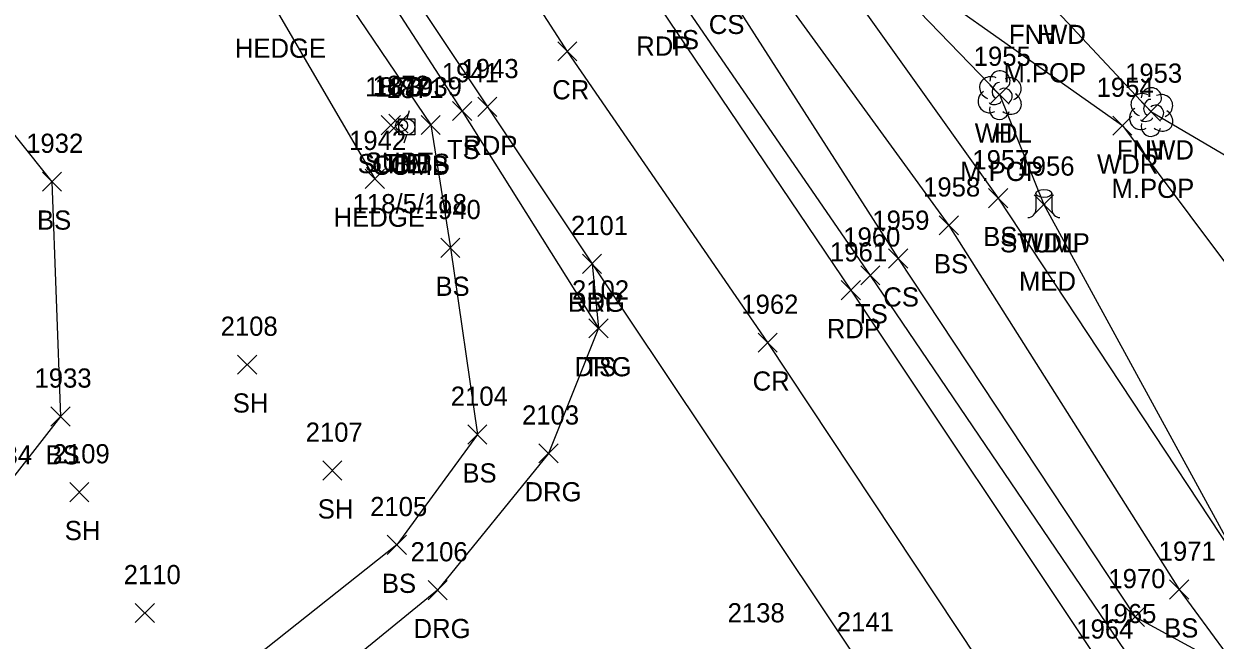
# Model space of a CAD drawing. Extents: x 1501299 to 1502485, y 381423 to 383765.
# Drawn here: x 1501473.5 to 1501597.6, y 383367.4 to 383431.6 of the extents above; entities that cross this region are included whole.
import ezdxf

# ---------------------------------------------------------------- set-up
doc = ezdxf.new("R2010")
doc.units = 0
for name, color, linetype in [('C_A', 7, 'Continuous'), ('C_I', 7, 'Continuous'), ('CBP', 7, 'Continuous'), ('L_A', 7, 'Continuous'), ('L_C', 7, 'Continuous'), ('L_I', 7, 'Continuous'), ('L_TIC', 7, 'Continuous'), ('LAHR', 7, 'Continuous'), ('LAWA', 7, 'Continuous'), ('LELB', 7, 'Continuous'), ('LFNC', 7, 'Continuous'), ('LTD', 7, 'Continuous'), ('LTS', 7, 'Continuous'), ('P_A', 7, 'Continuous'), ('P_I', 7, 'Continuous'), ('P_TIC', 7, 'Continuous'), ('PET', 7, 'Continuous'), ('PRC', 7, 'Continuous'), ('R_A', 7, 'Continuous'), ('R_I', 7, 'Continuous'), ('R_TIC', 7, 'Continuous'), ('RDG', 7, 'Continuous'), ('U_A', 7, 'Continuous'), ('U_C', 7, 'Continuous'), ('U_I', 7, 'Continuous'), ('U_TIC', 7, 'Continuous'), ('UP', 7, 'Continuous')]:
    doc.layers.add(name, color=color, linetype=linetype)

msp = doc.modelspace()

# ---------------------------------------------------------------- linework, layer by layer
at = {"layer": 'CBP'}
for radius in [0.625, 0.0833]:
    msp.add_circle((1501512.86, 383421.03), radius, dxfattribs=at)
at = {"layer": 'L_TIC'}
for points in [[(1501574.15, 383423.23), (1501576.15, 383425.23)], [(1501576.15, 383423.23), (1501574.15, 383425.23)], [(1501518.17, 383421.52), (1501520.17, 383423.52)], [(1501520.17, 383421.52), (1501518.17, 383423.52)], [(1501589.93, 383421.47), (1501591.93, 383423.47)], [(1501591.93, 383421.47), (1501589.93, 383423.47)], [(1501514.89, 383420.07), (1501516.89, 383422.07)], [(1501516.89, 383420.07), (1501514.89, 383422.07)], [(1501586.95, 383420), (1501588.95, 383422)], [(1501588.95, 383420), (1501586.95, 383422)], [(1501475.43, 383414.16), (1501477.43, 383416.16)], [(1501477.43, 383414.16), (1501475.43, 383416.16)], [(1501509.07, 383414.46), (1501511.07, 383416.46)], [(1501511.07, 383414.46), (1501509.07, 383416.46)], [(1501574.01, 383412.45), (1501576.01, 383414.45)], [(1501576.01, 383412.45), (1501574.01, 383414.45)], [(1501578.77, 383411.79), (1501580.77, 383413.79)], [(1501580.77, 383411.79), (1501578.77, 383413.79)], [(1501568.88, 383409.61), (1501570.88, 383411.61)], [(1501570.88, 383409.61), (1501568.88, 383411.61)], [(1501516.94, 383407.26), (1501518.94, 383409.26)], [(1501518.94, 383407.26), (1501516.94, 383409.26)], [(1501563.6, 383406.15), (1501565.6, 383408.15)], [(1501565.6, 383406.15), (1501563.6, 383408.15)], [(1501560.69, 383404.4), (1501562.69, 383406.4)], [(1501562.69, 383404.4), (1501560.69, 383406.4)], [(1501532.38, 383398.88), (1501534.38, 383400.88)], [(1501534.38, 383398.88), (1501532.38, 383400.88)], [(1501495.77, 383395.1), (1501497.77, 383397.1)], [(1501497.77, 383395.1), (1501495.77, 383397.1)], [(1501476.31, 383389.7), (1501478.31, 383391.7)], [(1501478.31, 383389.7), (1501476.31, 383391.7)], [(1501519.75, 383387.81), (1501521.75, 383389.81)], [(1501521.75, 383387.81), (1501519.75, 383389.81)], [(1501504.64, 383384.06), (1501506.64, 383386.06)], [(1501506.64, 383384.06), (1501504.64, 383386.06)], [(1501478.28, 383381.81), (1501480.28, 383383.81)], [(1501480.28, 383381.81), (1501478.28, 383383.81)], [(1501511.36, 383376.31), (1501513.36, 383378.31)], [(1501513.36, 383376.31), (1501511.36, 383378.31)], [(1501592.86, 383371.66), (1501594.86, 383373.66)], [(1501594.86, 383371.66), (1501592.86, 383373.66)], [(1501485.11, 383369.22), (1501487.11, 383371.22)], [(1501487.11, 383369.22), (1501485.11, 383371.22)], [(1501588.27, 383368.8), (1501590.27, 383370.8)], [(1501590.27, 383368.8), (1501588.27, 383370.8)]]:
    msp.add_lwpolyline(points, dxfattribs=at)
at = {"layer": 'LAHR'}
msp.add_lwpolyline([(1501486.06, 383454.74), (1501499.78, 383433.07), (1501510.07, 383415.46)], dxfattribs=at)
at = {"layer": 'LAWA'}
for points in [[(1501557.45, 383442.58), (1501575.15, 383424.23), (1501579.77, 383412.79), (1501600.51, 383374.82), (1501609.72, 383369.18), (1501618.19, 383374.12), (1501605.62, 383397.42)], [(1501557.45, 383442.58), (1501587.95, 383421), (1501605.62, 383397.42)]]:
    msp.add_lwpolyline(points, dxfattribs=at)
at = {"layer": 'LELB'}
for points in [[(1501358.62, 383732.98), (1501381.14, 383696.09), (1501398.69, 383667.71), (1501415.46, 383640.29), (1501435.3, 383603.99), (1501464.9, 383561.23), (1501485.32, 383525.1), (1501505.06, 383497.04), (1501522.93, 383468.15), (1501546.42, 383435.55), (1501564.6, 383407.15), (1501589.27, 383369.8), (1501600.38, 383363.76)], [(1501355.51, 383731.14), (1501378.37, 383693.86), (1501395.55, 383665.66), (1501411.45, 383638.21), (1501433.32, 383602.63), (1501461.34, 383558.64), (1501483.16, 383524.05), (1501502.07, 383494.51), (1501520.43, 383466.23), (1501542.02, 383433.96), (1501561.69, 383405.4), (1501588.28, 383366.16), (1501592.45, 383361.85)], [(1501332.79, 383719.08), (1501356.21, 383681.5), (1501373.29, 383652.69), (1501388.57, 383624.23), (1501410.59, 383588.65), (1501439.07, 383543.46), (1501460.07, 383509.46), (1501480.49, 383480.19), (1501499.63, 383452.74), (1501519.17, 383422.52), (1501533.38, 383399.88)], [(1501466.9, 383480.31), (1501471.6, 383467.81), (1501488.94, 383457.91), (1501495.79, 383450.81), (1501515.89, 383421.07), (1501517.94, 383408.26), (1501520.75, 383388.81), (1501512.36, 383377.31), (1501492.52, 383361.6), (1501470.5, 383349.33), (1501449.88, 383345.74), (1501440.32, 383348.07)], [(1501393.09, 383436.29), (1501422.55, 383449.61), (1501429.44, 383451.1), (1501440.2, 383445.83), (1501458.48, 383437.57), (1501476.43, 383415.16), (1501477.31, 383390.7), (1501471.1, 383382.7)], [(1501555.06, 383441.42), (1501575.01, 383413.45), (1501600.51, 383374.82)], [(1501550.47, 383437.33), (1501569.88, 383410.61), (1501593.86, 383372.66), (1501600.38, 383363.76), (1501609.16, 383365.94), (1501620.09, 383370.75), (1501635.69, 383377), (1501648.8, 383391.86)]]:
    msp.add_lwpolyline(points, dxfattribs=at)
at = {"layer": 'LFNC'}
msp.add_lwpolyline([(1501598.42, 383526.97), (1501583.57, 383507.22), (1501582.32, 383503.52), (1501551.42, 383461.96), (1501556.79, 383457.15), (1501570.08, 383443.83), (1501579.66, 383434.51), (1501590.93, 383422.47), (1501618.03, 383406.52), (1501631.82, 383398.73), (1501638.24, 383395.91), (1501648.8, 383391.86), (1501655.59, 383390.21)], dxfattribs=at)
at = {"layer": 'LTD'}
for p, q in [((1501575.15, 383424.23), (1501575.15, 383424.23)), ((1501575.15, 383424.23), (1501575.15, 383424.23)), ((1501590.93, 383422.47), (1501590.93, 383422.47)), ((1501590.93, 383422.47), (1501590.93, 383422.47))]:
    msp.add_line(p, q, dxfattribs=at)
for centre in [(1501575.2, 383425.66), (1501590.97, 383423.9)]:
    msp.add_arc(centre, 1.05, 335.5272, 180.9563, dxfattribs=at)
for centre, major_axis, ratio, start_param, end_param in [((1501574.36, 383424.9), (1.21, -0.51), 0.895232, 1.570796, 4.712389), ((1501576.19, 383424.81), (-1.14, -0.48), 0.949671, 1.570796, 4.712389), ((1501574.94, 383424.69), (-0.208, -0.792), 0.645439, 3.141593, 6.283185), ((1501575.65, 383424.06), (-0.5, 0.667), 0.989748, 3.141593, 6.283185), ((1501574.07, 383423.52), (0.58, -1.04), 0.959034, 3.141593, 6.283185), ((1501574.69, 383423.48), (-0.625, -0.083), 0.423636, 0, 3.141593), ((1501576.15, 383423.4), (-1.09, 0.79), 0.841452, 1.570796, 4.712389), ((1501590.14, 383423.14), (1.21, -0.51), 0.895232, 1.570796, 4.712389), ((1501590.72, 383422.93), (-0.208, -0.792), 0.645439, 3.141593, 6.283185), ((1501591.97, 383423.05), (-1.14, -0.48), 0.949671, 1.570796, 4.712389), ((1501575.15, 383422.73), (0.26, 1.06), 0.942809, 1.570796, 4.712389), ((1501589.84, 383421.76), (0.58, -1.04), 0.959034, 3.141593, 6.283185), ((1501591.43, 383422.3), (-0.5, 0.667), 0.989748, 3.141593, 6.283185), ((1501591.93, 383421.64), (-1.09, 0.79), 0.841452, 1.570796, 4.712389), ((1501590.93, 383420.97), (0.26, 1.06), 0.942809, 1.570796, 4.712389), ((1501590.47, 383421.72), (-0.625, -0.083), 0.423636, 0, 3.141593)]:
    msp.add_ellipse(centre, major_axis=major_axis, ratio=ratio, start_param=start_param, end_param=end_param, dxfattribs=at)
at = {"layer": 'LTS'}
for p, q in [((1501578.94, 383413.93), (1501578.94, 383412.26)), ((1501580.61, 383413.76), (1501580.61, 383413.93)), ((1501580.61, 383413.93), (1501580.61, 383412.26)), ((1501579.78, 383412.78), (1501579.78, 383412.78)), ((1501579.78, 383412.78), (1501579.78, 383412.78)), ((1501579.78, 383412.76), (1501579.78, 383412.76))]:
    msp.add_line(p, q, dxfattribs=at)
msp.add_circle((1501579.78, 383412.78), 0.0833, dxfattribs=at)
for centre, start, end in [((1501578.11, 383412.26), 270, 360), ((1501581.44, 383412.26), 180, 270)]:
    msp.add_arc(centre, 0.833, start, end, dxfattribs=at)
msp.add_ellipse((1501579.78, 383413.93), major_axis=(-0.833, 0), ratio=0.5, dxfattribs=at)
at = {"layer": 'P_TIC'}
for points in [[(1501529.12, 383427.74), (1501531.12, 383429.74)], [(1501531.12, 383427.74), (1501529.12, 383429.74)], [(1501520.79, 383421.95), (1501522.79, 383423.95)], [(1501522.79, 383421.95), (1501520.79, 383423.95)], [(1501531.7, 383405.6), (1501533.7, 383407.6)], [(1501533.7, 383405.6), (1501531.7, 383407.6)], [(1501558.66, 383402.85), (1501560.66, 383404.85)], [(1501560.66, 383402.85), (1501558.66, 383404.85)], [(1501549.99, 383397.39), (1501551.99, 383399.39)], [(1501551.99, 383397.39), (1501549.99, 383399.39)]]:
    msp.add_lwpolyline(points, dxfattribs=at)
at = {"layer": 'PET'}
for points in [[(1501352.61, 383730.1), (1501376.04, 383692.66), (1501392.89, 383664.45), (1501409.55, 383637.05), (1501431.22, 383601.01), (1501459.29, 383556.77), (1501480.73, 383522.39), (1501500.04, 383493.11), (1501518.67, 383465.09), (1501539.81, 383433.29), (1501559.66, 383403.85), (1501585.89, 383364.55), (1501607.04, 383333.42), (1501616.49, 383318.82), (1501608.79, 383312.41), (1501601.65, 383306.28)], [(1501334.83, 383720.25), (1501358.01, 383682.47), (1501375.27, 383653.98), (1501391.81, 383626.28), (1501413.67, 383590.16), (1501441.93, 383545.3), (1501463.31, 383511.64), (1501483.05, 383481.71), (1501501.39, 383453.56), (1501521.79, 383422.95), (1501532.7, 383406.6), (1501560.32, 383365.3), (1501580.55, 383335.85), (1501587.21, 383326.16), (1501601.65, 383306.28)]]:
    msp.add_lwpolyline(points, dxfattribs=at)
at = {"layer": 'PRC'}
msp.add_lwpolyline([(1501342.03, 383724.18), (1501367.31, 383687.9), (1501383.59, 383659.52), (1501401.02, 383631.48), (1501422.76, 383595.53), (1501451.02, 383550.58), (1501471.94, 383517.22), (1501491.45, 383487.69), (1501510.59, 383459), (1501530.12, 383428.74), (1501550.99, 383398.39), (1501579.41, 383355.49), (1501608.79, 383312.41)], dxfattribs=at)
at = {"layer": 'R_TIC'}
for points in [[(1501531.7, 383405.6), (1501533.7, 383407.6)], [(1501533.7, 383405.6), (1501531.7, 383407.6)], [(1501532.38, 383398.88), (1501534.38, 383400.88)], [(1501534.38, 383398.88), (1501532.38, 383400.88)], [(1501527.17, 383385.85), (1501529.17, 383387.85)], [(1501529.17, 383385.85), (1501527.17, 383387.85)], [(1501515.61, 383371.6), (1501517.61, 383373.6)], [(1501517.61, 383371.6), (1501515.61, 383373.6)]]:
    msp.add_lwpolyline(points, dxfattribs=at)
at = {"layer": 'RDG'}
msp.add_lwpolyline([(1501532.7, 383406.6), (1501533.38, 383399.88), (1501528.17, 383386.85), (1501516.61, 383372.6), (1501496, 383355.77), (1501474.51, 383343.33), (1501449.69, 383333.16), (1501433.05, 383350.15)], dxfattribs=at)
at = {"layer": 'U_TIC'}
for points in [[(1501511.53, 383420.2), (1501513.53, 383422.2)], [(1501513.53, 383420.2), (1501511.53, 383422.2)], [(1501510.74, 383420.04), (1501512.74, 383422.04)], [(1501512.74, 383420.04), (1501510.74, 383422.04)]]:
    msp.add_lwpolyline(points, dxfattribs=at)
at = {"layer": 'UP'}
for p, q in [((1501513.64, 383422.54), (1501513.39, 383421.71)), ((1501512.56, 383420.04), (1501512.56, 383421.71)), ((1501512.56, 383421.71), (1501514.23, 383421.71)), ((1501514.23, 383421.71), (1501514.23, 383420.04)), ((1501514.23, 383420.04), (1501512.56, 383420.04)), ((1501513.14, 383419.21), (1501513.39, 383420.04)), ((1501513.39, 383420.87), (1501513.39, 383420.87))]:
    msp.add_line(p, q, dxfattribs=at)
msp.add_circle((1501513.39, 383420.87), 0.833, dxfattribs=at)

# ---------------------------------------------------------------- texts
at = {"layer": 'C_A'}
msp.add_text('TIE', height=2, dxfattribs=at).set_placement((1501510.94, 383416.03))
at = {"layer": 'C_I'}
msp.add_text('1870', height=2, dxfattribs=at).set_placement((1501510.08, 383424.03))
at = {"layer": 'L_A'}
for s, p in [('CS', (1501544.86, 383430.55)), ('TS', (1501540.43, 383428.96)), ('FNWD', (1501576.13, 383429.51)), ('H', (1501579.1, 383429.51)), ('HEDGE', (1501495.48, 383428.07)), ('WDL', (1501572.57, 383419.23)), ('H', (1501574.58, 383419.23)), ('TS', (1501517.58, 383417.52)), ('FNWD', (1501587.39, 383417.47)), ('H', (1501590.36, 383417.47)), ('BS', (1501514.33, 383416.07)), ('WDR', (1501585.31, 383416)), ('HEDGE', (1501505.77, 383410.46)), ('BS', (1501474.87, 383410.16)), ('BS', (1501573.45, 383408.45)), ('STUMP', (1501575.2, 383407.79)), ('WDL', (1501577.19, 383407.79)), ('BS', (1501568.32, 383405.61)), ('BS', (1501516.38, 383403.26)), ('CS', (1501563.04, 383402.15)), ('TS', (1501560.1, 383400.4)), ('TS', (1501531.79, 383394.88)), ('SH', (1501495.26, 383391.1)), ('BS', (1501475.75, 383385.7)), ('BS', (1501519.19, 383383.81)), ('SH', (1501504.12, 383380.06)), ('SH', (1501477.76, 383377.81)), ('BS', (1501510.8, 383372.31)), ('BS', (1501592.3, 383367.66))]:
    msp.add_text(s, height=2, dxfattribs=at).set_placement(p)
at = {"layer": 'L_C'}
for s, p in [('M.POP', (1501575.56, 383425.51)), ('M.POP', (1501571.05, 383415.23)), ('M.POP', (1501586.82, 383413.47)), ('MED', (1501577.18, 383403.79))]:
    msp.add_text(s, height=2, dxfattribs=at).set_placement(p)
at = {"layer": 'L_I'}
for s, p in [('1955', (1501572.46, 383427.23)), ('1955', (1501572.46, 383427.23)), ('1941', (1501517.04, 383425.52)), ('1953', (1501588.23, 383425.47)), ('1953', (1501588.23, 383425.47)), ('1939', (1501513.19, 383424.07)), ('1954', (1501585.26, 383424)), ('1932', (1501473.74, 383418.16)), ('1942', (1501507.38, 383418.46)), ('1957', (1501572.32, 383416.45)), ('1956', (1501577.02, 383415.79)), ('1956', (1501577.02, 383415.79)), ('1958', (1501567.19, 383413.61)), ('1940', (1501515.16, 383411.26)), ('1959', (1501561.9, 383410.15)), ('1960', (1501558.87, 383408.4)), ('2102', (1501530.61, 383402.88)), ('2108', (1501494, 383399.1)), ('1933', (1501474.61, 383393.7)), ('2104', (1501517.98, 383391.81)), ('2107', (1501502.86, 383388.06)), ('1934', (1501468.41, 383385.7)), ('2109', (1501476.5, 383385.81)), ('2105', (1501509.58, 383380.31)), ('1971', (1501591.73, 383375.66)), ('2110', (1501483.9, 383373.22)), ('1970', (1501586.49, 383372.8)), ('1965', (1501585.54, 383369.16))]:
    msp.add_text(s, height=2, dxfattribs=at).set_placement(p)
at = {"layer": 'P_A'}
for s, p in [('RDP', (1501537.3, 383428.29)), ('CR', (1501528.55, 383423.74)), ('RDP', (1501519.28, 383417.95)), ('RDP', (1501530.19, 383401.6)), ('RDP', (1501557.15, 383398.85)), ('CR', (1501549.43, 383393.39))]:
    msp.add_text(s, height=2, dxfattribs=at).set_placement(p)
at = {"layer": 'P_I'}
for s, p in [('1943', (1501519.1, 383425.95)), ('2101', (1501530.5, 383409.6)), ('1961', (1501557.49, 383406.85)), ('1962', (1501548.25, 383401.39)), ('2141', (1501558.2, 383368.3)), ('1964', (1501583.15, 383367.55))]:
    msp.add_text(s, height=2, dxfattribs=at).set_placement(p)
at = {"layer": 'R_A'}
for p in [(1501530.19, 383401.6), (1501530.87, 383394.88), (1501525.66, 383381.85), (1501514.1, 383367.6)]:
    msp.add_text('DRG', height=2, dxfattribs=at).set_placement(p)
at = {"layer": 'R_I'}
for s, p in [('2101', (1501530.5, 383409.6)), ('2102', (1501530.61, 383402.88)), ('2103', (1501525.4, 383389.85)), ('2106', (1501513.79, 383375.6)), ('2138', (1501546.82, 383369.24)), ('2141', (1501558.2, 383368.3)), ('1964', (1501583.15, 383367.55))]:
    msp.add_text(s, height=2, dxfattribs=at).set_placement(p)
at = {"layer": 'U_A'}
for s, p in [('SUBE', (1501508.28, 383416.04)), ('SUBT', (1501509.03, 383416.2)), ('COMB', (1501509.78, 383415.87))]:
    msp.add_text(s, height=2, dxfattribs=at).set_placement(p)
at = {"layer": 'U_C'}
msp.add_text('118/5/118', height=2, dxfattribs=at).set_placement((1501507.76, 383411.87))
at = {"layer": 'U_I'}
for s, p in [('1873', (1501509.05, 383424.04)), ('1872', (1501509.84, 383424.2)), ('1871', (1501511.27, 383423.87))]:
    msp.add_text(s, height=2, dxfattribs=at).set_placement(p)

doc.saveas('drawing.dxf')
